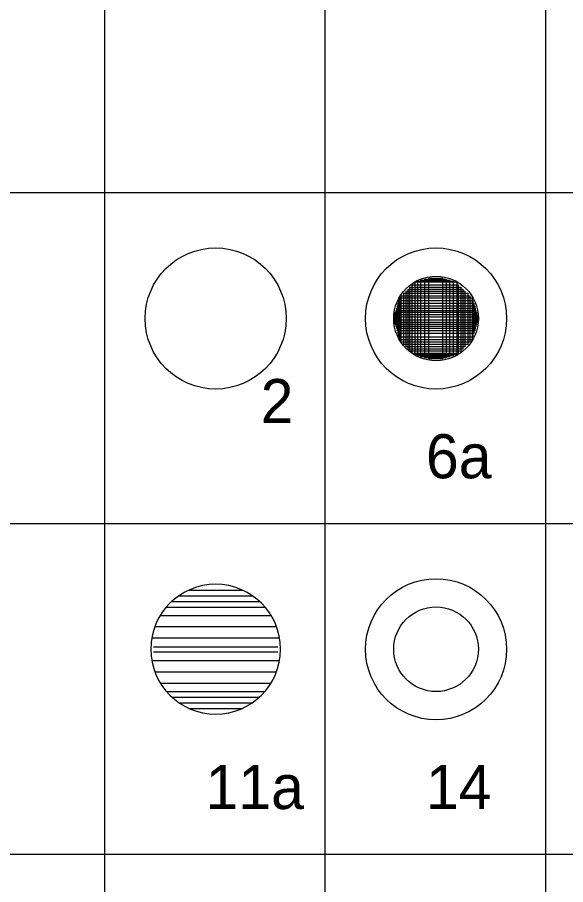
# Model space of a CAD drawing. Extents: x -28 to 822, y 61 to 665.
# Drawn here: x 109.16 to 134.04, y 260.35 to 299.69 of the extents above; entities that cross this region are included whole.
import ezdxf

# ---------------------------------------------------------------- set-up
doc = ezdxf.new("R2010")
doc.units = 0
doc.layers.add('KOLEJIŠTĚ', color=7, linetype='Continuous')

# ---------------------------------------------------------------- blocks, each defined once
blk = doc.blocks.new('HR3')
for radius in [2.5, 1.5]:
    blk.add_circle((0, 0), radius)
blk = doc.blocks.new('ZT72')
at = {"xscale": 0.8, "yscale": 0.8000000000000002}
blk.add_blockref('HR3', (0, 0), dxfattribs=at)
blk = doc.blocks.new('HR6')
for p, q in [((-1.304, 1.895), (1.304, 1.895)), ((-0.95, 2.095), (0.95, 2.095)), ((-1.555, 1.695), (1.555, 1.695)), ((-1.748, 1.495), (1.748, 1.495)), ((-1.962, 1.2), (1.962, 1.2)), ((-2.156, 0.8), (2.156, 0.8)), ((-2.265, 0.4), (2.265, 0.4)), ((-2.2, 0.09), (2.2, 0.09)), ((-2.2, -0.09), (2.2, -0.09)), ((-2.265, -0.4), (2.265, -0.4)), ((-2.156, -0.8), (2.156, -0.8)), ((-1.962, -1.2), (1.962, -1.2)), ((-1.748, -1.495), (1.748, -1.495)), ((-1.555, -1.695), (1.555, -1.695)), ((-1.304, -1.895), (1.304, -1.895)), ((-0.95, -2.095), (0.95, -2.095))]:
    blk.add_line(p, q)
for start, end in [(0, 180), (180, 0)]:
    blk.add_arc((0, 0), 2.3, start, end)
blk = doc.blocks.new('ZT75')
at = {"xscale": 0.8, "yscale": 0.8000000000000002}
blk.add_blockref('HR6', (0, 0), dxfattribs=at)

msp = doc.modelspace()

# ---------------------------------------------------------------- linework, layer by layer
for p, q in [((113.116, 381.738), (113.116, 111.738)), ((123.116, 381.738), (123.116, 111.738)), ((133.116, 381.738), (133.116, 141.738)), ((133.116, 336.738), (133.116, 111.738)), ((5.068, 291.738), (540.616, 291.738)), ((5.068, 276.738), (292.72, 276.738)), ((5.068, 261.738), (540.616, 261.738))]:
    msp.add_line(p, q)
for points in [[(129.165, 284.437), (127.072, 284.437), (127.072, 287.556), (129.165, 287.556)], [(129.101, 284.383), (127.208, 284.383), (127.208, 287.692), (129.101, 287.692)], [(128.937, 284.337), (127.326, 284.337), (127.326, 287.719), (128.937, 287.719)], [(128.764, 284.292), (127.472, 284.292), (127.472, 287.765), (128.764, 287.765)], [(128.609, 284.246), (127.645, 284.246), (127.645, 287.81), (128.609, 287.81)], [(128.455, 284.201), (127.836, 284.201), (127.836, 287.856), (128.455, 287.856)], [(129.592, 284.846), (126.698, 284.846), (126.698, 287.183), (129.592, 287.183)], [(129.465, 284.746), (126.799, 284.746), (126.799, 287.274), (129.465, 287.274)], [(129.365, 284.646), (126.89, 284.646), (126.89, 287.365), (129.365, 287.365)], [(129.274, 284.546), (126.971, 284.546), (126.971, 287.456), (129.274, 287.456)], [(129.829, 285.183), (126.471, 285.183), (126.471, 286.847), (129.829, 286.847)], [(129.802, 285.064), (126.507, 285.064), (126.507, 286.965), (129.802, 286.965)], [(129.683, 284.955), (126.571, 284.955), (126.571, 287.056), (129.683, 287.056)], [(129.965, 285.674), (126.353, 285.674), (126.353, 286.392), (129.965, 286.392)], [(129.938, 285.583), (126.371, 285.583), (126.371, 286.501), (129.938, 286.501)], [(129.911, 285.474), (126.407, 285.474), (126.407, 286.61), (129.911, 286.61)], [(129.874, 285.355), (126.435, 285.355), (126.435, 286.728), (129.874, 286.728)], [(130.047, 285.956), (126.28, 285.956), (126.28, 286.11), (130.047, 286.11)], [(129.984, 285.765), (126.307, 285.765), (126.307, 286.319), (129.984, 286.319)], [(130.011, 285.846), (126.307, 285.846), (126.307, 286.219), (130.011, 286.219)]]:
    msp.add_lwpolyline(points, close=True)
msp.add_circle((118.157, 286.031), 3.2)

# ---------------------------------------------------------------- block references
at = {"layer": 'KOLEJIŠTĚ', "xscale": 1.600000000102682, "yscale": 1.600000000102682}
for name, p in [('ZT72', (128.157, 286.031)), ('ZT72', (128.157, 271.031)), ('ZT75', (118.157, 271.031))]:
    msp.add_blockref(name, p, dxfattribs=at)

# ---------------------------------------------------------------- texts
for s, p in [('2', (120.198, 281.284)), ('6a', (127.698, 278.784)), ('11a', (117.698, 263.784)), ('14', (127.698, 263.784))]:
    msp.add_text(s, height=2).set_placement(p)

doc.saveas('drawing.dxf')
